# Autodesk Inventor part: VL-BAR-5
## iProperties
Created: 2005-08
Part Number: VL-BAR-5
Document SubType Name: Sheet Metal
Density: 1 g/cm^3
Mass: 0.845368 g
Surface Area: 16.5133 cm^2
Volume: 0.845368 cm^3
Sheet Metal Rule: Default
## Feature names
1. Rectangular Pattern1
2. Plate1
